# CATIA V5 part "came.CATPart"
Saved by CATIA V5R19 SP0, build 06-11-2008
Part number: came
Bounding box of the stored display mesh (mm): x -75 to 75, y -75 to 75, z 0 to 15
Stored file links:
  C:\Users\Alex\IFMA\2A\IAO\Modélisation\came.CATPart
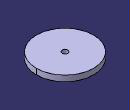
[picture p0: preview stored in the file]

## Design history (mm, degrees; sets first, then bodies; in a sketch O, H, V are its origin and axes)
Body1 (main body)
  Sketch1 on xy-plane, origin (0, 0, 0), H (1, 0, 0), V (0, 1, 0)
    circle A1 centre (0, 0) radius 75
    radius A1 = 75
  Pad1: profile Sketch1, direction (0, 0, 1), length 15
  Sketch2 on end face of Pad1, origin (0, 0, 15), H (1, 0, 0), V (0, 1, 0)
    point P1 (0, 0)
    reference projected circle E1 centre (0, 0) radius 75 from edge [face of Pad1 from Sketch1.A1 | end face of Pad1]
    concentricity: P1 E1
  Hole1: placed by Sketch2, at (0, 0, 15) direction (0, 0, -1), diameter 15, through (limit type 3)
